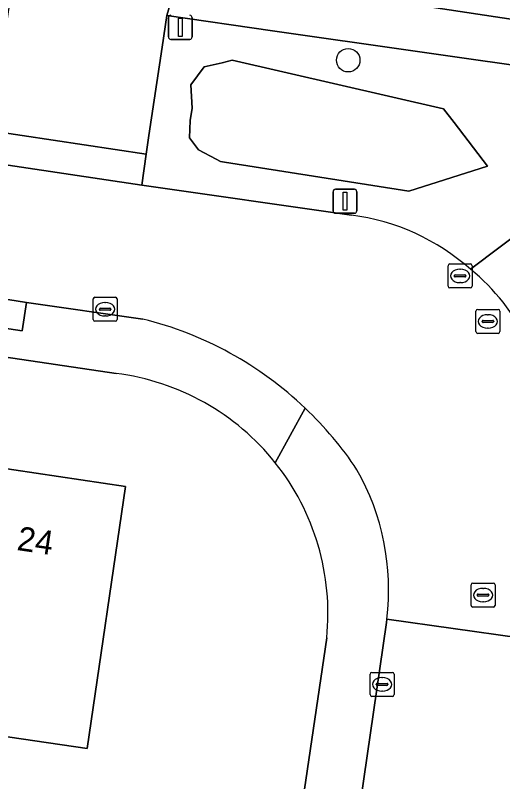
# Model space of a CAD drawing. Extents: x 164148 to 165261, y 382513 to 383432.
# Drawn here: x 164659.65 to 164679.94, y 383144.67 to 383176.55 of the extents above; entities that cross this region are included whole.
import ezdxf

# ---------------------------------------------------------------- set-up
doc = ezdxf.new("R2010")
doc.units = 0
for name, color, linetype in [('IMGEO_Afsluitpaal', 7, 'Continuous'), ('IMGEO_Boom', 7, 'Continuous'), ('IMGEO_Erf', 7, 'Continuous'), ('IMGEO_Greppel_droge_sloot', 7, 'Continuous'), ('IMGEO_Groenvoorziening', 7, 'Continuous'), ('IMGEO_Kolk', 7, 'Continuous'), ('IMGEO_Lichtmast', 7, 'Continuous'), ('IMGEO_Pand', 7, 'Continuous'), ('IMGEO_Pand_nummerreeks', 7, 'Continuous'), ('IMGEO_Rijbaan_lokaal_open', 7, 'Continuous'), ('IMGEO_Rioolput', 7, 'Continuous'), ('IMGEO_Voetpad_open', 7, 'Continuous')]:
    doc.layers.add(name, color=color, linetype=linetype)

msp = doc.modelspace()

# ---------------------------------------------------------------- linework, layer by layer
at = {"layer": 'IMGEO_Afsluitpaal'}
for p, q in [((164666.022, 383175.653), (164666.022, 383176.453)), ((164666.022, 383176.453), (164666.022, 383175.653)), ((164667.012, 383176.453), (164667.012, 383175.653)), ((164667.012, 383175.653), (164667.012, 383176.453)), ((164666.912, 383175.553), (164666.122, 383175.553)), ((164666.122, 383175.553), (164666.912, 383175.553))]:
    msp.add_line(p, q, dxfattribs=at)
msp.add_lwpolyline([(164666.442, 383176.428), (164666.592, 383176.428), (164666.592, 383175.678), (164666.442, 383175.678), (164666.442, 383176.428)], dxfattribs=at)
for centre, start, end in [((164666.122, 383176.453), 90, 180), ((164666.122, 383176.453), 90, 180), ((164666.912, 383176.453), 0, 90), ((164666.912, 383176.453), 360, 90), ((164666.122, 383175.653), 180, 270), ((164666.122, 383175.653), 180, 270), ((164666.912, 383175.653), 270, 0), ((164666.912, 383175.653), 270, 0)]:
    msp.add_arc(centre, 0.1, start, end, dxfattribs=at)
at = {"layer": 'IMGEO_Boom'}
msp.add_circle((164673.509, 383174.684), 0.489, dxfattribs=at)
at = {"layer": 'IMGEO_Erf'}
for points in [[(164663.846, 383161.649), (164628.573, 383166.874)], [(164623.816, 383163.728), (164623.27, 383160.3), (164619.179, 383132.443), (164618.352, 383126.809), (164615.891, 383110.249), (164614.945, 383103.98), (164613.433, 383093.793), (164612.816, 383089.325), (164610.85, 383076.068), (164610.275, 383072.012), (164608.947, 383063.175), (164608.549, 383060.35), (164603.815, 383028.066), (164603.697, 383027.909), (164653.403, 383020.558), (164672.613, 383150.649)]]:
    msp.add_lwpolyline(points, dxfattribs=at)
msp.add_lwpolyline([(164654.241, 383156.308), (164657.409, 383155.838), (164657.717, 383157.915), (164664.244, 383156.948), (164662.644, 383146.041), (164656.094, 383147.008), (164656.393, 383149.091), (164653.238, 383149.558)], close=True, dxfattribs=at)
for centre, radius, start, end in [((164662.606, 383151.668), 10.058, 38.5507, 82.9195), ((164662.608, 383151.668), 10.056, 354.1867, 38.56)]:
    msp.add_arc(centre, radius, start, end, dxfattribs=at)
at = {"layer": 'IMGEO_Greppel_droge_sloot'}
msp.add_lwpolyline([(164668.684, 383174.68), (164668.257, 383174.581), (164667.51, 383174.41), (164666.96, 383173.659), (164667.011, 383172.691), (164666.932, 383172.178), (164666.909, 383171.462), (164667.273, 383170.961), (164668.007, 383170.572), (164668.194, 383170.474), (164668.365, 383170.447), (164676.035, 383169.24), (164679.305, 383170.28), (164677.913, 383172.089), (164677.473, 383172.66)], close=True, dxfattribs=at)
at = {"layer": 'IMGEO_Groenvoorziening'}
for points in [[(164666.516, 383178.455), (164670.634, 383177.868), (164690.397, 383174.87), (164691.919, 383176.015)], [(164670.356, 383175.908), (164665.956, 383176.551), (164665.759, 383175.226), (164665.214, 383171.552), (164665.099, 383170.779), (164664.911, 383169.492), (164673.645, 383168.239)], [(164678.601, 383165.984), (164688.374, 383173.342), (164670.356, 383175.908)]]:
    msp.add_lwpolyline(points, dxfattribs=at)
msp.add_lwpolyline([(164677.473, 383172.66), (164677.913, 383172.089), (164679.305, 383170.28), (164676.035, 383169.24), (164668.365, 383170.447), (164668.194, 383170.474), (164668.007, 383170.572), (164667.273, 383170.961), (164666.909, 383171.462), (164666.932, 383172.178), (164667.011, 383172.691), (164666.96, 383173.659), (164667.51, 383174.41), (164668.257, 383174.581), (164668.684, 383174.68)], close=True, dxfattribs=at)
msp.add_arc((164672.46, 383159.061), 9.254, 48.4251, 82.6435, dxfattribs=at)
at = {"layer": 'IMGEO_Kolk'}
for p, q in [((164662.89, 383163.898), (164662.89, 383164.75)), ((164662.965, 383164.824), (164663.817, 383164.824)), ((164663.378, 383164.604), (164663.403, 383164.604)), ((164663.891, 383164.75), (164663.891, 383163.898)), ((164663.149, 383164.318), (164663.149, 383164.33)), ((164663.587, 383164.281), (164663.189, 383164.281)), ((164663.192, 383164.367), (164663.59, 383164.367)), ((164663.633, 383164.33), (164663.633, 383164.318)), ((164663.401, 383164.044), (164663.376, 383164.044)), ((164663.817, 383163.824), (164662.965, 383163.824)), ((164674.42, 383148.288), (164674.42, 383149.14)), ((164674.495, 383149.214), (164675.347, 383149.214)), ((164674.908, 383148.994), (164674.933, 383148.994)), ((164675.421, 383149.14), (164675.421, 383148.288)), ((164674.679, 383148.708), (164674.679, 383148.72)), ((164675.117, 383148.671), (164674.719, 383148.671)), ((164674.722, 383148.757), (164675.12, 383148.757)), ((164675.163, 383148.72), (164675.163, 383148.708)), ((164674.931, 383148.434), (164674.906, 383148.434)), ((164675.347, 383148.214), (164674.495, 383148.214))]:
    msp.add_line(p, q, dxfattribs=at)
for points in [[(164662.89, 383163.898), (164662.89, 383164.75)], [(164662.965, 383164.824), (164663.817, 383164.824)], [(164663.891, 383164.75), (164663.891, 383163.898)], [(164663.817, 383163.824), (164662.965, 383163.824)], [(164674.42, 383148.288), (164674.42, 383149.14)], [(164674.495, 383149.214), (164675.347, 383149.214)], [(164675.421, 383149.14), (164675.421, 383148.288)], [(164675.347, 383148.214), (164674.495, 383148.214)]]:
    msp.add_lwpolyline(points, dxfattribs=at)
for centre, radius, start, end in [((164662.967, 383164.748), 0.0765, 91.552, 178.448), ((164662.967, 383164.748), 0.0765, 91.552, 178.448), ((164663.815, 383164.748), 0.0765, 1.552, 88.448), ((164663.815, 383164.748), 0.0765, 1.552, 88.448), ((164663.189, 383164.327), 0.0403, 85.8775, 175.7526), ((164663.186, 383164.317), 0.0366, 178.938, 274.7102), ((164663.59, 383164.324), 0.043, 264.8664, 352.4533), ((164663.594, 383164.329), 0.0386, 1.7309, 96.639), ((164662.967, 383163.9), 0.0765, 181.552, 268.448), ((164662.967, 383163.9), 0.0765, 181.552, 268.448), ((164663.815, 383163.9), 0.0765, 271.552, 358.448), ((164663.815, 383163.9), 0.0765, 271.552, 358.448), ((164674.497, 383149.138), 0.0765, 91.552, 178.448), ((164674.497, 383149.138), 0.0765, 91.552, 178.448), ((164675.345, 383149.138), 0.0765, 1.552, 88.448), ((164675.345, 383149.138), 0.0765, 1.552, 88.448), ((164674.719, 383148.717), 0.0403, 85.8775, 175.7526), ((164674.716, 383148.707), 0.0366, 178.938, 274.7102), ((164675.12, 383148.714), 0.043, 264.8664, 352.4533), ((164675.124, 383148.719), 0.0386, 1.7309, 96.639), ((164674.497, 383148.29), 0.0765, 181.552, 268.448), ((164674.497, 383148.29), 0.0765, 181.552, 268.448), ((164675.345, 383148.29), 0.0765, 271.552, 358.448), ((164675.345, 383148.29), 0.0765, 271.552, 358.448)]:
    msp.add_arc(centre, radius, start, end, dxfattribs=at)
for centre, major_axis, ratio, start_param, end_param in [((164663.377, 383164.324), (-0.387, 0.002), 0.722429, 4.712389, 7.853982), ((164663.402, 383164.324), (-0.39, 0.002), 0.717154, 1.570796, 4.712389), ((164674.907, 383148.714), (-0.387, 0.002), 0.722429, 4.712389, 7.853982), ((164674.932, 383148.714), (-0.39, 0.002), 0.717154, 1.570796, 4.712389)]:
    msp.add_ellipse(centre, major_axis=major_axis, ratio=ratio, start_param=start_param, end_param=end_param, dxfattribs=at)
at = {"layer": 'IMGEO_Lichtmast'}
for p, q in [((164672.878, 383168.414), (164672.878, 383169.214)), ((164672.878, 383169.214), (164672.878, 383168.414)), ((164672.978, 383169.314), (164673.768, 383169.314)), ((164673.768, 383169.314), (164672.978, 383169.314)), ((164673.868, 383169.214), (164673.868, 383168.414)), ((164673.868, 383168.414), (164673.868, 383169.214)), ((164673.768, 383168.314), (164672.978, 383168.314)), ((164672.978, 383168.314), (164673.768, 383168.314))]:
    msp.add_line(p, q, dxfattribs=at)
msp.add_lwpolyline([(164673.298, 383169.189), (164673.448, 383169.189), (164673.448, 383168.439), (164673.298, 383168.439), (164673.298, 383169.189)], dxfattribs=at)
for centre, start, end in [((164672.978, 383169.214), 90, 180), ((164672.978, 383169.214), 90, 180), ((164673.768, 383169.214), 0, 90), ((164673.768, 383169.214), 360, 90), ((164672.978, 383168.414), 180, 270), ((164672.978, 383168.414), 180, 270), ((164673.768, 383168.414), 270, 0), ((164673.768, 383168.414), 270, 0)]:
    msp.add_arc(centre, 0.1, start, end, dxfattribs=at)
at = {"layer": 'IMGEO_Pand'}
msp.add_lwpolyline([(164662.644, 383146.041), (164664.244, 383156.948), (164657.717, 383157.915), (164657.409, 383155.838), (164654.241, 383156.308), (164653.238, 383149.558), (164656.393, 383149.091), (164656.094, 383147.008)], close=True, dxfattribs=at)
at = {"layer": 'IMGEO_Rijbaan_lokaal_open'}
for points in [[(164673.645, 383168.239), (164664.911, 383169.492), (164658.417, 383170.457), (164632.948, 383174.244), (164632.072, 383168.777), (164654.931, 383165.435), (164660.12, 383164.603), (164664.962, 383163.916)], [(164675.111, 383151.432), (164680.645, 383150.644), (164681.714, 383158.045)], [(164680.414, 383148.922), (164680.645, 383150.644), (164675.111, 383151.432), (164675.108, 383151.287), (164672.668, 383134.547), (164671.889, 383129.204), (164671.68, 383127.772), (164677.103, 383126.885), (164677.839, 383131.639)]]:
    msp.add_lwpolyline(points, dxfattribs=at)
msp.add_lwpolyline([(164658.635, 383171.748), (164658.417, 383170.457), (164664.911, 383169.492), (164665.099, 383170.779)], close=True, dxfattribs=at)
for centre, radius, start, end in [((164672.46, 383159.061), 9.254, 48.4251, 82.6435), ((164673.192, 383159.29), 8.606, 25.389, 51.0601), ((164661.326, 383149.279), 15.082, 46.4276, 76.0479), ((164661.32, 383149.278), 15.087, 33.6876, 46.4149), ((164665.188, 383152.685), 10.002, 352.801, 29.7337)]:
    msp.add_arc(centre, radius, start, end, dxfattribs=at)
at = {"layer": 'IMGEO_Rioolput'}
for p, q in [((164677.741, 383166.209), (164678.593, 383166.209)), ((164677.666, 383165.283), (164677.666, 383166.135)), ((164678.154, 383165.989), (164678.179, 383165.989)), ((164678.667, 383166.135), (164678.667, 383165.283)), ((164677.925, 383165.703), (164677.925, 383165.715)), ((164678.363, 383165.666), (164677.965, 383165.666)), ((164677.968, 383165.752), (164678.366, 383165.752)), ((164678.409, 383165.715), (164678.409, 383165.703)), ((164678.177, 383165.429), (164678.152, 383165.429)), ((164678.593, 383165.209), (164677.741, 383165.209)), ((164678.898, 383164.316), (164679.75, 383164.316)), ((164678.823, 383163.39), (164678.823, 383164.242)), ((164679.311, 383164.096), (164679.336, 383164.096)), ((164679.824, 383164.242), (164679.824, 383163.39)), ((164679.082, 383163.81), (164679.082, 383163.822)), ((164679.52, 383163.773), (164679.122, 383163.773)), ((164679.125, 383163.859), (164679.523, 383163.859)), ((164679.566, 383163.822), (164679.566, 383163.81)), ((164679.75, 383163.316), (164678.898, 383163.316)), ((164679.334, 383163.536), (164679.309, 383163.536)), ((164678.623, 383152.002), (164678.623, 383152.854)), ((164678.698, 383152.928), (164679.55, 383152.928)), ((164679.624, 383152.854), (164679.624, 383152.002)), ((164678.925, 383152.471), (164679.323, 383152.471)), ((164679.111, 383152.708), (164679.136, 383152.708)), ((164678.882, 383152.422), (164678.882, 383152.434)), ((164679.32, 383152.385), (164678.922, 383152.385)), ((164679.134, 383152.148), (164679.109, 383152.148)), ((164679.366, 383152.434), (164679.366, 383152.422)), ((164679.55, 383151.928), (164678.698, 383151.928))]:
    msp.add_line(p, q, dxfattribs=at)
for points in [[(164677.741, 383166.209), (164678.593, 383166.209)], [(164677.666, 383165.283), (164677.666, 383166.135)], [(164678.667, 383166.135), (164678.667, 383165.283)], [(164678.593, 383165.209), (164677.741, 383165.209)], [(164678.898, 383164.316), (164679.75, 383164.316)], [(164678.823, 383163.39), (164678.823, 383164.242)], [(164679.824, 383164.242), (164679.824, 383163.39)], [(164679.75, 383163.316), (164678.898, 383163.316)], [(164678.623, 383152.002), (164678.623, 383152.854)], [(164678.698, 383152.928), (164679.55, 383152.928)], [(164679.624, 383152.854), (164679.624, 383152.002)], [(164679.55, 383151.928), (164678.698, 383151.928)]]:
    msp.add_lwpolyline(points, dxfattribs=at)
for centre, radius, start, end in [((164677.743, 383166.133), 0.0765, 91.552, 178.448), ((164677.743, 383166.133), 0.0765, 91.552, 178.448), ((164678.591, 383166.133), 0.0765, 1.552, 88.448), ((164678.591, 383166.133), 0.0765, 1.552, 88.448), ((164677.965, 383165.712), 0.0403, 85.8775, 175.7526), ((164677.962, 383165.702), 0.0366, 178.938, 274.7102), ((164678.366, 383165.709), 0.043, 264.8664, 352.4533), ((164678.37, 383165.714), 0.0386, 1.7309, 96.639), ((164677.743, 383165.285), 0.0765, 181.552, 268.448), ((164677.743, 383165.285), 0.0765, 181.552, 268.448), ((164678.591, 383165.285), 0.0765, 271.552, 358.448), ((164678.591, 383165.285), 0.0765, 271.552, 358.448), ((164678.9, 383164.24), 0.0765, 91.552, 178.448), ((164678.9, 383164.24), 0.0765, 91.552, 178.448), ((164679.748, 383164.24), 0.0765, 1.552, 88.448), ((164679.748, 383164.24), 0.0765, 1.552, 88.448), ((164679.122, 383163.819), 0.0403, 85.8775, 175.7526), ((164679.119, 383163.809), 0.0366, 178.938, 274.7102), ((164679.523, 383163.816), 0.043, 264.8664, 352.4533), ((164679.527, 383163.821), 0.0386, 1.7309, 96.639), ((164678.9, 383163.392), 0.0765, 181.552, 268.448), ((164678.9, 383163.392), 0.0765, 181.552, 268.448), ((164679.748, 383163.392), 0.0765, 271.552, 358.448), ((164679.748, 383163.392), 0.0765, 271.552, 358.448), ((164678.7, 383152.852), 0.0765, 91.552, 178.448), ((164678.7, 383152.852), 0.0765, 91.552, 178.448), ((164679.548, 383152.852), 0.0765, 1.552, 88.448), ((164679.548, 383152.852), 0.0765, 1.552, 88.448), ((164678.922, 383152.431), 0.0403, 85.8775, 175.7526), ((164679.327, 383152.433), 0.0386, 1.7309, 96.639), ((164678.919, 383152.421), 0.0366, 178.938, 274.7102), ((164679.323, 383152.428), 0.043, 264.8664, 352.4533), ((164678.7, 383152.004), 0.0765, 181.552, 268.448), ((164678.7, 383152.004), 0.0765, 181.552, 268.448), ((164679.548, 383152.004), 0.0765, 271.552, 358.448), ((164679.548, 383152.004), 0.0765, 271.552, 358.448)]:
    msp.add_arc(centre, radius, start, end, dxfattribs=at)
for centre, major_axis, ratio, start_param, end_param in [((164678.153, 383165.709), (-0.387, 0.002), 0.722429, 4.712389, 7.853982), ((164678.178, 383165.709), (-0.39, 0.002), 0.717154, 1.570796, 4.712389), ((164679.31, 383163.816), (-0.387, 0.002), 0.722429, 4.712389, 7.853982), ((164679.335, 383163.816), (-0.39, 0.002), 0.717154, 1.570796, 4.712389), ((164679.11, 383152.428), (-0.387, 0.002), 0.722429, 4.712389, 7.853982), ((164679.135, 383152.428), (-0.39, 0.002), 0.717154, 1.570796, 4.712389)]:
    msp.add_ellipse(centre, major_axis=major_axis, ratio=ratio, start_param=start_param, end_param=end_param, dxfattribs=at)
at = {"layer": 'IMGEO_Voetpad_open'}
for points in [[(164665.956, 383176.551), (164666.516, 383178.455), (164659.857, 383179.434), (164659.475, 383177.492), (164659.384, 383176.872), (164659.358, 383176.693), (164658.635, 383171.748), (164665.099, 383170.779), (164665.214, 383171.552), (164665.759, 383175.226)], [(164670.634, 383177.868), (164666.516, 383178.455), (164665.956, 383176.551), (164670.356, 383175.908), (164688.374, 383173.342), (164690.397, 383174.87)], [(164654.931, 383165.435), (164654.74, 383164.206), (164659.936, 383163.43), (164660.12, 383164.603)]]:
    msp.add_lwpolyline(points, close=True, dxfattribs=at)
for points in [[(164691.919, 383176.015), (164690.397, 383174.87), (164688.374, 383173.342), (164678.601, 383165.984)], [(164664.962, 383163.916), (164660.12, 383164.603), (164659.936, 383163.43), (164654.74, 383164.206), (164654.931, 383165.435), (164632.072, 383168.777)], [(164628.573, 383166.874), (164663.846, 383161.649)], [(164671.721, 383160.206), (164670.472, 383157.936)], [(164670.472, 383157.936), (164671.721, 383160.206)], [(164666.161, 383090.76), (164664.995, 383090.947), (164665.754, 383095.997), (164666.957, 383095.84), (164669.137, 383110.698), (164667.959, 383110.888), (164668.674, 383115.736), (164669.899, 383115.549), (164671.68, 383127.772), (164671.889, 383129.204), (164670.698, 383129.426), (164671.449, 383134.735), (164672.668, 383134.547), (164675.108, 383151.287), (164675.111, 383151.432)], [(164672.613, 383150.649), (164653.403, 383020.558), (164653.018, 383017.951), (164651.876, 383010.215), (164651.419, 383007.225), (164650.705, 383001.947), (164653.078, 383001.462), (164657.714, 383033.452), (164656.509, 383033.621), (164657.237, 383038.501), (164658.441, 383038.338), (164659.675, 383046.714), (164660.382, 383051.508), (164663.299, 383071.06), (164663.405, 383071.768), (164663.423, 383071.905), (164662.198, 383072.123), (164662.932, 383077.035), (164664.173, 383076.85), (164666.161, 383090.76)]]:
    msp.add_lwpolyline(points, dxfattribs=at)
for centre, radius, start, end in [((164673.192, 383159.29), 8.606, 25.389, 51.0601), ((164661.326, 383149.279), 15.082, 46.4276, 76.0479), ((164662.606, 383151.668), 10.058, 38.5507, 82.9195), ((164661.32, 383149.278), 15.087, 33.6876, 46.4149), ((164662.608, 383151.668), 10.056, 354.1867, 38.56), ((164665.188, 383152.685), 10.002, 352.801, 29.7337)]:
    msp.add_arc(centre, radius, start, end, dxfattribs=at)

# ---------------------------------------------------------------- texts
at = {"layer": 'IMGEO_Pand_nummerreeks'}
msp.add_text('24', height=1, rotation=351.5718, dxfattribs=at).set_placement((164659.684, 383154.308))

doc.saveas('drawing.dxf')
